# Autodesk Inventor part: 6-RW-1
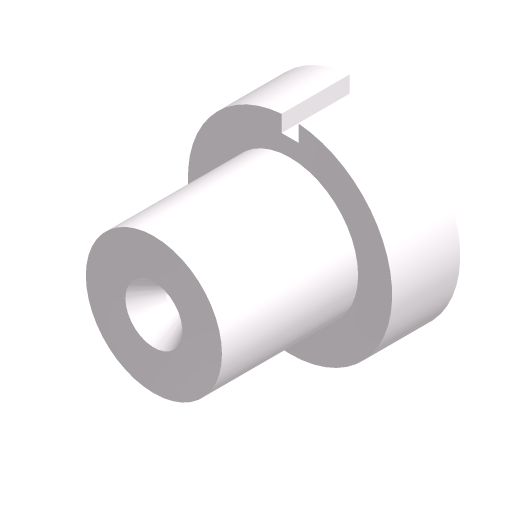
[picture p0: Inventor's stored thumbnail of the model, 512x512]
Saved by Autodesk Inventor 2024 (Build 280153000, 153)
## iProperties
Company: ATC
Shininess: 20.0
Length Units: 11269
Angle Units: 11279
Time Units: 11290
Mass Units: 11283
Length Display Precision: 3
Angle Display Precision: 2
Created: 2023-03
Part Number: 6-RW-1
Document SubType Name: Modeling
Designer: Andrzej Jaskulski
Material: Kurs-AJ
Density: 1 g/cm^3
Appearance: Kurs-AJ
Checked By: A.J.
Engr Approved By: Andrzej Jaskulski
Mfg Approved By: Andrzej Jaskulski
Authority: A.J.
Density: 0.0
Volumn: 0.0
Area: 0.0
PropertySet Name: Model Information
Control State: 0
Master: False
Checked Out: False
Title: A.J.: Kurs R2024-MEP
Author: Andrzej Jaskulski
Revision Number: 1/24
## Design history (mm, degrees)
node "Czop środkowy" dims "d1" = 4, "d2" = 0
node "Płaszczyzna konstrukcyjna6"
workaxis "Work Axis1"
node "Czop końcowy" dims "d5" = 8, "d6" = 0
node "Nakiełek" dims "d9" = 1.6, "d10" = 3.35, "d11" = 2, "d12" = 60 deg, "d13" = 4.3, "d14" = 120 deg, "d30" = 6
sketch "Szkic5"
  geometry: L1 (0, -0.8)-(0, 4.8) reference; L2 (-6, 4)-(6, 4) reference; L3 (-6, 0)-(6, 0) reference; L4 (-0.5, 4)-(0.5, 4); L5 (0.5, 4)-(0.5, 0); L6 (0.5, 0)-(-0.5, 0); L7 (-0.5, 0)-(-0.5, 4); 2 further points
  constraints: 8 end point, 4 midpoint, 2 parallel, 1 horizontal, 1 perpendicular
  dimensions: "d37" = 1 distance between parallel lines of L5 L7
extrude "Wyciągnięcie proste4" cut sketch "Szkic5" distance "d38" = 1; taper "d39" = 0 deg
node "Bryła1"
node "Korpusy bryłowe"
node "Korpusy powierzchniowe"
sketch "Sketch1"
  geometry: C1 r 6 at (0, 0)
  constraints: 1 centre point, 1 other
  dimensions: "d3" = 12 diameter of C1
sketch "Sketch2"
  geometry: C1 r 6 at (0, 0); C2 r 4 at (0, 0)
  constraints: 2 centre point, 1 coincident
  dimensions: "d4" = 8 diameter of C2
sketch "Sketch3"
  geometry: C1 r 4 at (0, 0) reference; 1 further point
  constraints: 1 coincident
other parameters: "d24" = 45 (derived), "dlugosc" = 16 [user parameter]
